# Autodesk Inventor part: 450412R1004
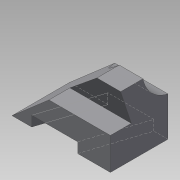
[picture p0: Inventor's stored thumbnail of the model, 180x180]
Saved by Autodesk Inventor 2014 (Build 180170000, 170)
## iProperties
Created: 2015-04
Part Number: 450412R1004
Material: Generic
Document SubType Name: Modeling
Designer: 203-01
Density: 1 g/cm^3
Appearance: Default
Author: 203-01
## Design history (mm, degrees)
sketch "스케치1"
  geometry: L1 (-67.5, -39.5)-(67.5, -39.5); L2 (67.5, -39.5)-(67.5, 39.5); L3 (67.5, 39.5)-(-67.5, 39.5); L4 (-67.5, 39.5)-(-67.5, -39.5); L5 (-67.5, -39.5)-(67.5, 39.5); L6 (67.5, -39.5)-(-67.5, 39.5); 1 further point
  constraints: 12 end point, 2 midpoint, 2 parallel, 1 horizontal, 1 perpendicular
  dimensions: "d0" = 135 distance of L3.end L2.end; "d1" = 79 distance of L2.end L1.end
extrude "돌출1" new body sketch "스케치1" distance "d2" = 89; taper "d3" = 0 deg
sketch "스케치2"
  geometry: L1 (0, 0)-(135, 0) reference; L2 (0, 89)-(135, 89) reference; L3 (0, 0)-(0, 89) reference; L4 (0, 0)-(102.383, 89); L5 (0, 89)-(102.383, 89); L6 (0, 89)-(0, 0); 1 further point
  constraints: 6 end point, 2 collinear, 1 point on line
  dimensions: "d5" = 139 deg angle of L1 L4
extrude "돌출2" cut sketch "스케치2" stored distance "d6" = 0; taper "d7" = 0 deg
sketch "스케치3"
  geometry: L1 (0, 79)-(-89, 79) reference; L2 (-89, 0)-(-89, 79) reference; L3 (0, 0)-(-89, 0) reference; L4 (-44, 28.713)-(-132.37, 0); L5 (-44, 28.713)-(-44, 0); L6 (-132.37, 0)-(-44, 0); C1 r 44 at (-97, 88); 1 further point
  constraints: 6 end point, 1 centre point, 1 collinear, 1 perpendicular, 1 point on line
  dimensions: "d9" = 44 radius of C1; "d10" = 8 distance from line of C1.centre L2; "d11" = 9 distance from line of L1 C1.centre; "d13" = 44 distance from line of point (0, 39.5) L5; "d14" = 72 deg angle of L4 L5; "d15" = 88.37037 distance from line of L4.end L5
extrude "돌출3" cut sketch "스케치3" stored distance "d16" = 89; taper "d17" = 0 deg
sketch "스케치4"
  geometry: L1 (-67.5, 39.5)-(-67.5, -39.5) reference; L2 (-16.884, -39.5)-(-67.5, -39.5) reference; L3 (67.5, -39.5)-(-16.884, -39.5) reference; L4 (-5.46, 39.5)-(67.5, 39.5) reference; L5 (-67.5, 39.5)-(-5.46, 39.5) reference; L6 (-40.5, -39.5)-(-14.831, 39.5); L7 (22.588, -39.5)-(48.256, 39.5); 1 further point
  constraints: 4 end point, 4 point on line, 1 parallel
  dimensions: "d18" = 27 distance of L6.start L1.end; "d19" = 60 distance between parallel lines of L7 L6; "d20" = 72 deg angle of L4 L7
extrude "돌출4" cut sketch "스케치4" distance "d21" = 14; taper "d22" = 0 deg
node "솔리드1"
